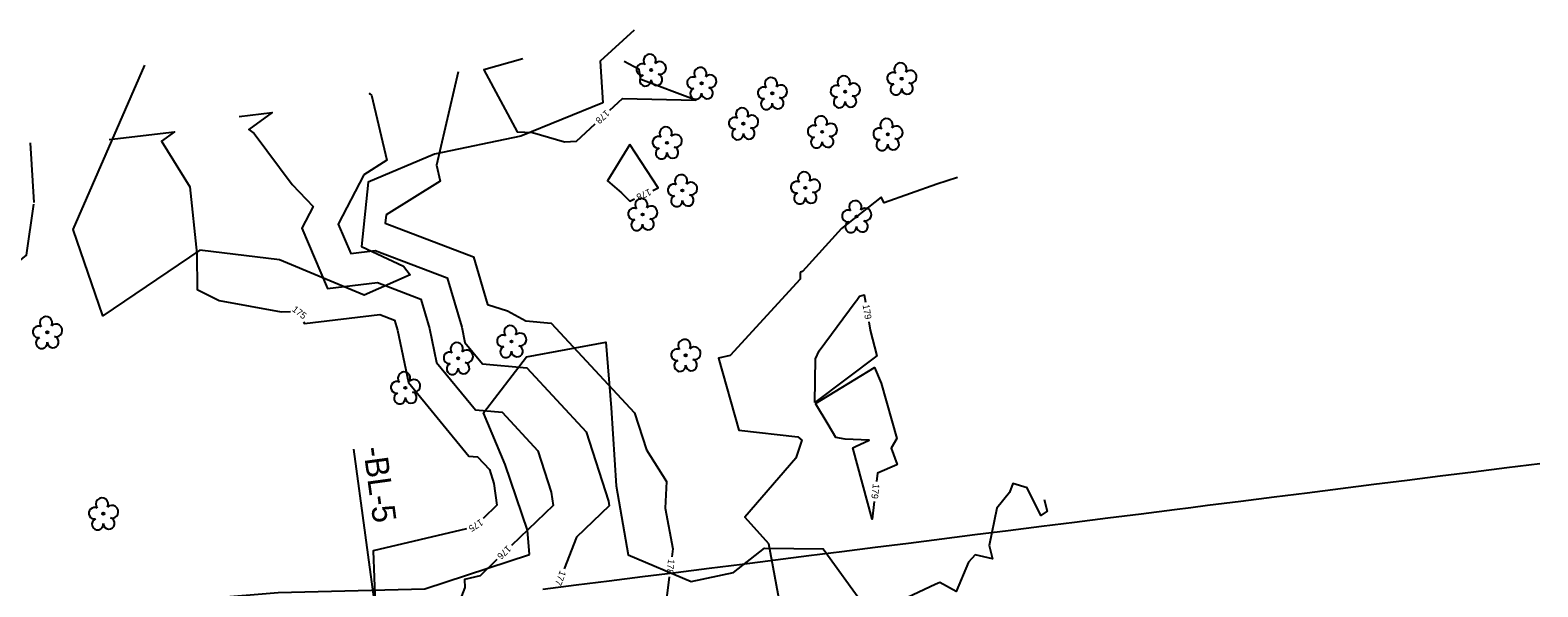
# Model space of a CAD drawing. Extents: x 2086416 to 2115205, y 575507 to 632762.
# Drawn here: x 2112506.7 to 2112956.5, y 581854.9 to 582021 of the extents above; entities that cross this region are included whole.
import ezdxf

# ---------------------------------------------------------------- set-up
doc = ezdxf.new("R2010")
doc.units = 0
for name, color, linetype in [('Default', 7, 'Continuous'), ('DTM Contours Major', 7, 'Continuous'), ('DTM Contours Major Text', 7, 'Continuous'), ('DTM Contours Minor', 7, 'Continuous'), ('DTM Contours Minor Text', 7, 'Continuous'), ('Exist Hydro Stream or Body of Water', 7, 'Continuous'), ('Exist Hydrographic FEMA Cross Section', 7, 'Continuous'), ('Exist Vegetation Tree CELL', 7, 'Continuous'), ('Exist Vegetation Woods Line', 7, 'Continuous')]:
    doc.layers.add(name, color=color, linetype=linetype)

# ---------------------------------------------------------------- blocks, each defined once
blk = doc.blocks.new('EXIST VEGETATION TREE')
at = {"layer": 'Exist Vegetation Tree CELL'}
blk.add_line((0, 0), (0, 0), dxfattribs=at)
blk.add_circle((0, 0), 0.00652, dxfattribs=at)
for centre, radius, start, end in [((-0.0077, 0.0575), 0.0371, 330.16508, 219.71335), ((-0.0521, 0.0031), 0.0345, 62.66361, 279.3457), ((0.051, 0.0118), 0.038, 257.1011, 134.19993), ((-0.0341, -0.0624), 0.0338, 111.56708, 6.23104), ((0.0335, -0.058), 0.034, 181.28216, 74.55999)]:
    blk.add_arc(centre, radius, start, end, dxfattribs=at)

msp = doc.modelspace()

# ---------------------------------------------------------------- linework, layer by layer
at = {"layer": 'Default'}
msp.add_line((2112618.34, 581785.48), (2112603.31, 581895.93), dxfattribs=at)
at = {"layer": 'DTM Contours Major'}
for points in [[(2112530.33, 581988.32), (2112549.79, 581990.63), (2112545.96, 581987.84), (2112554.39, 581974.22), (2112556.43, 581954.31), (2112556.54, 581943.61), (2112563.16, 581940.32), (2112581.6, 581936.89), (2112584.37, 581937.01)], [(2112588.3, 581933.96), (2112588.54, 581933.4), (2112611.09, 581936.12), (2112615.45, 581934.46), (2112616.32, 581931.49), (2112619.57, 581915.83), (2112637.59, 581893.89), (2112640.23, 581893.66), (2112643.78, 581889.84), (2112645.11, 581885.71), (2112646, 581879.24), (2112641.84, 581875.22)], [(2112809.21, 581880.92), (2112810.15, 581877.4), (2112808.25, 581876.11), (2112804.19, 581884.42), (2112799.94, 581885.7), (2112798.96, 581883.05), (2112795.09, 581878.3), (2112792.8, 581867.19), (2112793.8, 581863.22), (2112788.72, 581864.42), (2112786.67, 581862.19), (2112783.05, 581853.47), (2112778.14, 581856.17), (2112776.69, 581855.59), (2112770.17, 581852.49), (2112764.94, 581849.97), (2112763.7, 581843.17), (2112762.85, 581841.49), (2112758.53, 581840.84), (2112753.83, 581839.3)], [(2112636.91, 581872.16), (2112609.11, 581865.6), (2112609.65, 581849.73), (2112605.74, 581839.73), (2112603.91, 581826.98), (2112600.43, 581825.74), (2112595.52, 581824.65), (2112581.05, 581823.24), (2112575.88, 581822.78), (2112572.42, 581822.47)]]:
    msp.add_lwpolyline(points, dxfattribs=at)
at = {"layer": 'DTM Contours Minor'}
for points in [[(2112634.45, 582008.48), (2112627.92, 581980.65), (2112629.04, 581975.94), (2112612.99, 581965.84), (2112612.66, 581963.36), (2112639.04, 581953.3), (2112643.19, 581939.14), (2112649.11, 581937.25), (2112654.63, 581934.18), (2112662.19, 581933.53), (2112687.01, 581906.75), (2112690.57, 581895.74), (2112696.57, 581886.25), (2112696.17, 581878.3), (2112698.48, 581866.21), (2112698.18, 581863.81)], [(2112653.7, 582012.41), (2112642.08, 582009.12), (2112652.06, 581990.6), (2112656.59, 581990.41), (2112666.11, 581987.66), (2112669.76, 581987.86), (2112675.29, 581992.98)], [(2112679.7, 581997.06), (2112683.5, 582000.58), (2112705.37, 582000.1), (2112688.91, 582006.27), (2112688.46, 582009.25), (2112683.91, 582011.56)], [(2112607.92, 582002.07), (2112608.11, 582002.1), (2112607.98, 582002), (2112608.07, 582001.93), (2112608.55, 582001.6), (2112613.18, 581982.13), (2112606.28, 581977.79), (2112598.66, 581963.08), (2112602.41, 581954.36), (2112609.63, 581955.23), (2112631.18, 581947.02), (2112635.49, 581932.32), (2112636.43, 581927.76), (2112641.68, 581921.37), (2112654.87, 581920.24), (2112672.6, 581901.11), (2112679.28, 581880.46), (2112679.47, 581879.08), (2112669.7, 581869.66), (2112666.03, 581860.19)], [(2112569.13, 581995.2), (2112578.95, 581996.36), (2112571.97, 581991.28), (2112573.56, 581990.15), (2112584.87, 581974.86), (2112591.12, 581968.36), (2112587.74, 581961.85), (2112595.48, 581943.88), (2112610.36, 581945.68), (2112623.31, 581940.74), (2112625.9, 581931.9), (2112628, 581921.8), (2112639.64, 581907.63), (2112647.55, 581906.95), (2112658.19, 581895.47), (2112662.19, 581883.08), (2112662.73, 581879.16), (2112650.29, 581867.15)], [(2112685.61, 581986.83), (2112679.02, 581975.97), (2112683.15, 581972.38), (2112685.61, 581969.9), (2112687.08, 581970.59)], [(2112692.52, 581973.13), (2112694.14, 581973.88), (2112685.61, 581986.83)], [(2112783.36, 581977.02), (2112777.19, 581974.97), (2112761.48, 581969.46), (2112760.6, 581971.11), (2112748.83, 581961.81), (2112737.15, 581948.97), (2112737.17, 581948.9), (2112736.59, 581948.77), (2112736.48, 581948.58), (2112736.45, 581946.62), (2112715.55, 581923.9), (2112712.14, 581923.08), (2112718.12, 581901.59), (2112735.77, 581899.6), (2112736.98, 581898.61), (2112735.12, 581893.24), (2112719.92, 581875.62), (2112727.03, 581867.76), (2112730.62, 581848.49), (2112730.03, 581845.59), (2112728.71, 581844.64)], [(2112740.87, 581909.91), (2112741.04, 581922.86), (2112742.15, 581925.25), (2112752.84, 581939.75), (2112753.33, 581940.44), (2112754.21, 581941.58), (2112755.57, 581941.96), (2112755.94, 581939.82)], [(2112756.96, 581933.91), (2112757.38, 581931.47), (2112759.31, 581923.8), (2112740.87, 581909.91)], [(2112741.03, 581909.53), (2112758.65, 581920.34), (2112760.58, 581915.64), (2112765.28, 581899.13), (2112763.57, 581896.22), (2112765.38, 581891.36), (2112765.35, 581891.28), (2112759.53, 581888.79), (2112759.25, 581886.28)], [(2112758.57, 581880.32), (2112757.97, 581875.07), (2112752.2, 581896.38), (2112753, 581896.77), (2112757.02, 581898.67), (2112749.9, 581898.97), (2112747.13, 581899.46), (2112744.8, 581903.27), (2112741.03, 581909.53)], [(2112645.97, 581862.98), (2112640.96, 581858.15), (2112636.36, 581857.07), (2112636.44, 581854.64), (2112629.82, 581837.7), (2112626.77, 581831.69), (2112626.76, 581830.54), (2112626.08, 581830.21), (2112625.08, 581829.94), (2112613.9, 581825.94), (2112596.28, 581822.03), (2112595.89, 581821.94), (2112595.73, 581821.92), (2112595.14, 581821.86), (2112576.22, 581820.18), (2112561.06, 581818.84), (2112546.35, 581817.4), (2112536.87, 581816.69), (2112528.13, 581815.99), (2112511.43, 581814.74), (2112498.22, 581813.69), (2112487.5, 581812.49), (2112476.22, 581810.87), (2112468.78, 581810.01)], [(2112697.42, 581857.86), (2112695.28, 581840.91), (2112692.79, 581837.25), (2112690.56, 581835.55), (2112688.56, 581835.37), (2112677.37, 581832.83), (2112675.87, 581832.17), (2112672.05, 581831.94), (2112651.52, 581827.43), (2112646.49, 581826.71), (2112636.31, 581823.94), (2112625.7, 581822.28), (2112615.6, 581819.85), (2112596.09, 581816.86), (2112588.69, 581816.19), (2112577.09, 581814.47), (2112556.48, 581811.43), (2112547.27, 581811.07), (2112547.04, 581811.16), (2112539.5, 581810.54), (2112538.76, 581810.37), (2112520.89, 581808.45), (2112518.28, 581808.23), (2112517.45, 581808.07)]]:
    msp.add_lwpolyline(points, dxfattribs=at)
at = {"layer": 'Exist Hydro Stream or Body of Water'}
for points in [[(2112507.88, 581969.56), (2112506.82, 581987.31)], [(2112499.44, 581880.39), (2112494.24, 581935.71), (2112497.4, 581947.12), (2112505.67, 581953.82), (2112507.86, 581969.07)]]:
    msp.add_lwpolyline(points, dxfattribs=at)
at = {"layer": 'Exist Hydrographic FEMA Cross Section'}
msp.add_lwpolyline([(2112957.19, 581891.61), (2112947.27, 581890.36), (2112937.35, 581889.11), (2112927.44, 581887.86), (2112917.52, 581886.61), (2112907.6, 581885.35), (2112897.69, 581884.1), (2112887.77, 581882.85), (2112877.85, 581881.6), (2112867.94, 581880.35), (2112858.02, 581879.1), (2112853.06, 581878.47), (2112848.1, 581877.85), (2112838.18, 581876.59), (2112828.27, 581875.34), (2112818.35, 581874.09), (2112808.43, 581872.84), (2112798.52, 581871.59), (2112788.6, 581870.34), (2112778.68, 581869.08), (2112768.77, 581867.83), (2112758.85, 581866.58), (2112748.93, 581865.33), (2112739.02, 581864.08), (2112729.1, 581862.83), (2112719.18, 581861.57), (2112709.27, 581860.32), (2112699.35, 581859.07), (2112689.43, 581857.82), (2112679.52, 581856.57), (2112669.6, 581855.32), (2112659.68, 581854.07)], dxfattribs=at)
at = {"layer": 'Exist Vegetation Tree CELL'}
for p, q in [((2112691.99, 582009.07), (2112691.99, 582009.07)), ((2112707.05, 582005.1), (2112707.05, 582005.1)), ((2112766.77, 582006.45), (2112766.77, 582006.45)), ((2112728.14, 582002.08), (2112728.14, 582002.08)), ((2112749.88, 582002.61), (2112749.88, 582002.61)), ((2112719.53, 581993.06), (2112719.53, 581993.06)), ((2112743.04, 581990.61), (2112743.04, 581990.61)), ((2112696.75, 581987.34), (2112696.75, 581987.34)), ((2112762.6, 581989.85), (2112762.6, 581989.85)), ((2112701.33, 581973.1), (2112701.33, 581973.1)), ((2112738.03, 581973.92), (2112738.03, 581973.92)), ((2112689.45, 581965.97), (2112689.45, 581965.97)), ((2112753.29, 581965.35), (2112753.29, 581965.35)), ((2112702.3, 581923.94), (2112702.3, 581923.94))]:
    msp.add_line(p, q, dxfattribs=at)
for centre in [(2112691.99, 582009.07), (2112707.05, 582005.1), (2112766.77, 582006.45), (2112728.14, 582002.08), (2112749.88, 582002.61), (2112719.53, 581993.06), (2112743.04, 581990.61), (2112762.6, 581989.85), (2112696.75, 581987.34), (2112701.33, 581973.1), (2112738.03, 581973.92), (2112689.45, 581965.97), (2112753.29, 581965.35), (2112702.3, 581923.94)]:
    msp.add_circle(centre, 0.326, dxfattribs=at)
for centre, radius, start, end in [((2112691.6, 582011.94), 1.86, 330.1651, 219.7134), ((2112689.38, 582009.22), 1.73, 62.6636, 279.3457), ((2112694.54, 582009.66), 1.9, 257.1011, 134.1999), ((2112706.66, 582007.97), 1.86, 330.1651, 219.7134), ((2112764.17, 582006.61), 1.73, 62.6636, 279.3457), ((2112766.39, 582009.33), 1.86, 330.1651, 219.7134), ((2112769.32, 582007.04), 1.9, 257.1011, 134.1999), ((2112690.29, 582005.95), 1.69, 111.5671, 6.231), ((2112693.66, 582006.17), 1.7, 181.2822, 74.56), ((2112704.44, 582005.25), 1.73, 62.6636, 279.3457), ((2112708.72, 582002.2), 1.7, 181.2822, 74.56), ((2112709.6, 582005.69), 1.9, 257.1011, 134.1999), ((2112725.53, 582002.24), 1.73, 62.6636, 279.3457), ((2112727.75, 582004.96), 1.86, 330.1651, 219.7134), ((2112730.69, 582002.67), 1.9, 257.1011, 134.1999), ((2112747.27, 582002.76), 1.73, 62.6636, 279.3457), ((2112749.49, 582005.48), 1.86, 330.1651, 219.7134), ((2112752.43, 582003.2), 1.9, 257.1011, 134.1999), ((2112765.07, 582003.33), 1.69, 111.5671, 6.231), ((2112768.44, 582003.55), 1.7, 181.2822, 74.56), ((2112705.34, 582001.98), 1.69, 111.5671, 6.231), ((2112726.43, 581998.96), 1.69, 111.5671, 6.231), ((2112729.81, 581999.19), 1.7, 181.2822, 74.56), ((2112748.17, 581999.49), 1.69, 111.5671, 6.231), ((2112751.55, 581999.71), 1.7, 181.2822, 74.56), ((2112716.93, 581993.21), 1.73, 62.6636, 279.3457), ((2112719.15, 581995.93), 1.86, 330.1651, 219.7134), ((2112722.08, 581993.65), 1.9, 257.1011, 134.1999), ((2112742.65, 581993.48), 1.86, 330.1651, 219.7134), ((2112696.37, 581990.21), 1.86, 330.1651, 219.7134), ((2112717.83, 581989.94), 1.69, 111.5671, 6.231), ((2112721.21, 581990.16), 1.7, 181.2822, 74.56), ((2112740.43, 581990.76), 1.73, 62.6636, 279.3457), ((2112745.59, 581991.2), 1.9, 257.1011, 134.1999), ((2112760, 581990), 1.73, 62.6636, 279.3457), ((2112762.22, 581992.72), 1.86, 330.1651, 219.7134), ((2112765.15, 581990.44), 1.9, 257.1011, 134.1999), ((2112694.15, 581987.49), 1.73, 62.6636, 279.3457), ((2112695.05, 581984.22), 1.69, 111.5671, 6.231), ((2112698.42, 581984.44), 1.7, 181.2822, 74.56), ((2112699.3, 581987.92), 1.9, 257.1011, 134.1999), ((2112741.33, 581987.49), 1.69, 111.5671, 6.231), ((2112744.71, 581987.71), 1.7, 181.2822, 74.56), ((2112760.9, 581986.73), 1.69, 111.5671, 6.231), ((2112764.28, 581986.95), 1.7, 181.2822, 74.56), ((2112700.94, 581975.97), 1.86, 330.1651, 219.7134), ((2112737.64, 581976.8), 1.86, 330.1651, 219.7134), ((2112698.72, 581973.25), 1.73, 62.6636, 279.3457), ((2112703.88, 581973.69), 1.9, 257.1011, 134.1999), ((2112735.42, 581974.08), 1.73, 62.6636, 279.3457), ((2112736.33, 581970.8), 1.69, 111.5671, 6.231), ((2112739.7, 581971.02), 1.7, 181.2822, 74.56), ((2112740.58, 581974.51), 1.9, 257.1011, 134.1999), ((2112686.84, 581966.13), 1.73, 62.6636, 279.3457), ((2112689.06, 581968.85), 1.86, 330.1651, 219.7134), ((2112691.99, 581966.56), 1.9, 257.1011, 134.1999), ((2112699.62, 581969.98), 1.69, 111.5671, 6.231), ((2112703, 581970.2), 1.7, 181.2822, 74.56), ((2112752.9, 581968.22), 1.86, 330.1651, 219.7134), ((2112755.84, 581965.94), 1.9, 257.1011, 134.1999), ((2112687.74, 581962.85), 1.69, 111.5671, 6.231), ((2112691.12, 581963.07), 1.7, 181.2822, 74.56), ((2112750.68, 581965.5), 1.73, 62.6636, 279.3457), ((2112751.58, 581962.23), 1.69, 111.5671, 6.231), ((2112754.96, 581962.45), 1.7, 181.2822, 74.56), ((2112701.92, 581926.82), 1.86, 330.1651, 219.7134), ((2112699.7, 581924.1), 1.73, 62.6636, 279.3457), ((2112703.97, 581921.04), 1.7, 181.2822, 74.56), ((2112704.85, 581924.53), 1.9, 257.1011, 134.1999), ((2112700.6, 581920.82), 1.69, 111.5671, 6.231)]:
    msp.add_arc(centre, radius, start, end, dxfattribs=at)
at = {"layer": 'Exist Vegetation Woods Line'}
for points in [[(2112686.98, 582020.95), (2112676.77, 582011.73), (2112677.57, 581999.24)], [(2112677.57, 581999.24), (2112653.14, 581989.31), (2112627.34, 581983.99), (2112607.58, 581975.6), (2112605.63, 581956.42), (2112618.13, 581950.51), (2112620.06, 581947.91), (2112606.43, 581941.86), (2112581.12, 581952.43), (2112557.4, 581955.36), (2112528.38, 581935.68), (2112519.58, 581961.49), (2112540.98, 582010.48)], [(2112655.73, 581864.5), (2112655.15, 581871.73), (2112648.45, 581891.34), (2112642, 581906.74), (2112654.8, 581923.48), (2112678.53, 581927.89), (2112680.12, 581908.28), (2112681.57, 581885.02), (2112685.12, 581864.41), (2112703.96, 581856.48), (2112716.53, 581859.17), (2112725.8, 581866.44), (2112743.31, 581866.23), (2112755.55, 581849.31)], [(2112455.71, 581861.8), (2112519.59, 581848.11), (2112580.68, 581853.15), (2112624.48, 581854.23), (2112655.73, 581864.5)]]:
    msp.add_lwpolyline(points, dxfattribs=at)

# ---------------------------------------------------------------- block references
at = {"layer": 'Exist Vegetation Tree CELL', "xscale": 50, "yscale": 50}
for p in [(2112511.85, 581930.78), (2112650.35, 581928.07), (2112634.41, 581923.03), (2112618.69, 581914.24), (2112528.56, 581876.67)]:
    msp.add_blockref('EXIST VEGETATION TREE', p, dxfattribs=at)

# ---------------------------------------------------------------- texts
at = {"layer": 'Default'}
msp.add_text('-BL-5', height=7, rotation=277.7482, dxfattribs=at).set_placement((2112606.06, 581896.31))
at = {"layer": 'DTM Contours Major Text'}
for rotation, p in [(322.2519, (2112584.7, 581937.32)), (211.8619, (2112641.08, 581875.19))]:
    msp.add_text('175', height=2, rotation=rotation, dxfattribs=at).set_placement(p)
at = {"layer": 'DTM Contours Minor Text'}
for s, rotation, p in [('178', 222.7914, (2112678.48, 581997.3)), ('178', 204.9808, (2112691.44, 581973.73)), ('179', 279.7954, (2112755.07, 581938.94)), ('179', 263.5174, (2112758.17, 581885.67)), ('176', 223.9707, (2112649.07, 581867.37)), ('177', 248.7915, (2112664.84, 581859.88)), ('178', 262.8009, (2112697.09, 581863.22))]:
    msp.add_text(s, height=2, rotation=rotation, dxfattribs=at).set_placement(p)

doc.saveas('drawing.dxf')
